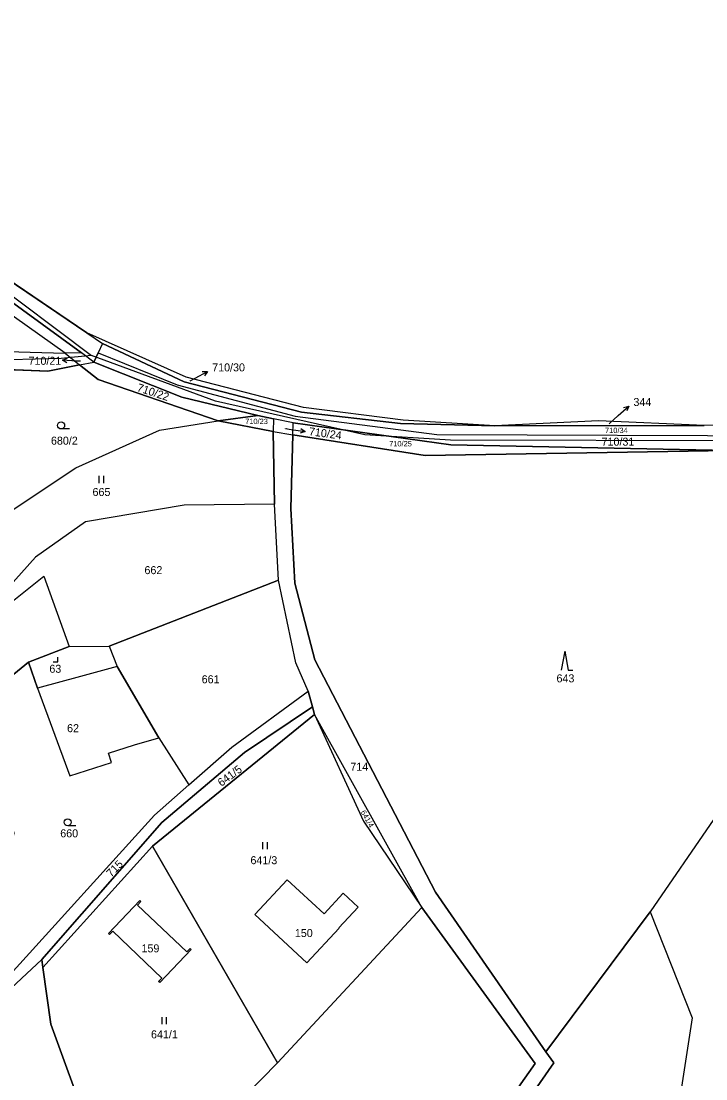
# Model space of a CAD drawing. Extents: x -590606 to -587796, y -1065936 to -1062515.
# Drawn here: x -589558.4 to -589413.2, y -1064760.8 to -1064536.2 of the extents above; entities that cross this region are included whole.
import ezdxf

# ---------------------------------------------------------------- set-up
doc = ezdxf.new("R2010")
doc.units = 0
for name, color, linetype in [('Cesty', 7, 'Continuous'), ('Parcela nároku', 7, 'Continuous'), ('Parcelní číslo', 7, 'Continuous'), ('Vnější obvod_ Studené', 7, 'Continuous'), ('Vrstva 30', 7, 'Continuous')]:
    doc.layers.add(name, color=color, linetype=linetype)

msp = doc.modelspace()

# ---------------------------------------------------------------- linework, layer by layer
at = {"layer": 'Cesty'}
for points in [[(-589892.17, -1064369.93), (-589875.26, -1064390.63), (-589869.59, -1064400.17), (-589860.61, -1064415.28), (-589855.62, -1064428.91), (-589851.76, -1064436.47), (-589835.09, -1064454.08), (-589818.14, -1064470.08), (-589809.98, -1064474.85), (-589789.91, -1064479.31), (-589769.84, -1064483.14), (-589746.37, -1064490.42), (-589728.15, -1064501.15), (-589708.7, -1064515.97), (-589695.75, -1064525.84), (-589673.94, -1064537.99), (-589648.4, -1064547.43), (-589623.17, -1064553.21), (-589602.26, -1064563.18), (-589592.55, -1064571.88), (-589566.17, -1064590.19), (-589543.56, -1064607.17)], [(-589312.39, -1064575.92), (-589318.72, -1064584.83), (-589335.76, -1064596.6), (-589354.95, -1064613.9), (-589370.21, -1064620.11), (-589392.14, -1064624.65), (-589405.6, -1064625.31), (-589467.35, -1064625.2), (-589485.5, -1064624.04), (-589517.23, -1064616.87), (-589543.56, -1064607.17), (-589549.94, -1064607.84), (-589566.34, -1064608.24), (-589595.98, -1064606.38), (-589632.73, -1064602.69), (-589650.77, -1064600.08), (-589699.72, -1064596.26), (-589711.59, -1064596.2), (-589764.62, -1064605.69), (-589799.36, -1064611.91)]]:
    msp.add_lwpolyline(points, dxfattribs=at)
at = {"layer": 'Parcela nároku'}
for points in [[(-589386.23, -1064621.24), (-589413.51, -1064622.05), (-589435.93, -1064621.07), (-589457.96, -1064622.14), (-589477.4, -1064620.92), (-589498.57, -1064618.24), (-589523.41, -1064611.81), (-589544.52, -1064602.39), (-589570.02, -1064585.07), (-589593.92, -1064567.75), (-589602.81, -1064558), (-589627.14, -1064547.63), (-589640.22, -1064546.2), (-589655.82, -1064541.47), (-589688.24, -1064525.96)], [(-589681.45, -1064532.18), (-589655.82, -1064541.47), (-589647.67, -1064545.57), (-589640.22, -1064546.2), (-589617.67, -1064553.05), (-589599.87, -1064563.44), (-589593.92, -1064567.75), (-589591.52, -1064570.55), (-589570.02, -1064585.07), (-589544.52, -1064602.39), (-589541.19, -1064604.66), (-589542.09, -1064606.65), (-589543.01, -1064608.6), (-589545.68, -1064606.61), (-589574.93, -1064585.33), (-589584.07, -1064579.7), (-589592.41, -1064573.65), (-589595.48, -1064570.57), (-589606.26, -1064560.21), (-589627.8, -1064551.78), (-589646.88, -1064549.01), (-589693.05, -1064528.65)], [(-589850.56, -1064625.55), (-589808.34, -1064612.83), (-589752.19, -1064600.19), (-589738.08, -1064597.9), (-589710.88, -1064593.56), (-589696.02, -1064593.97), (-589645.99, -1064597.91), (-589599.74, -1064604.8), (-589596.03, -1064605.35), (-589549.09, -1064606.72), (-589546.05, -1064609.19), (-589552.79, -1064610.5), (-589564.95, -1064610.02), (-589586.36, -1064609.18), (-589594.13, -1064607.9), (-589600.62, -1064606.83), (-589651.05, -1064601), (-589706.94, -1064597.01), (-589710.09, -1064597.48), (-589753, -1064605.14), (-589810.83, -1064617.52), (-589850.49, -1064629.2)], [(-589475.36, -1064794.48), (-589449.38, -1064757.57), (-589473.46, -1064724.46), (-589496.18, -1064683.43), (-589496.63, -1064681.82), (-589497.56, -1064678.5), (-589500.15, -1064672.47), (-589503.84, -1064654.9), (-589504.71, -1064638.79), (-589504.98, -1064623.35), (-589500.84, -1064624.06), (-589501.22, -1064639.68), (-589500.39, -1064655.52), (-589496.13, -1064671.82), (-589470.54, -1064721.2), (-589447.12, -1064755.09), (-589445.45, -1064757.41), (-589471.15, -1064794.54)]]:
    msp.add_lwpolyline(points, dxfattribs=at)
for points in [[(-589592.41, -1064573.65), (-589584.07, -1064579.7), (-589574.93, -1064585.33), (-589545.68, -1064606.61), (-589549.09, -1064606.72), (-589592.68, -1064575.78)], [(-589592.68, -1064575.78), (-589596.03, -1064605.35), (-589549.09, -1064606.72)], [(-589498.57, -1064618.24), (-589523.41, -1064611.81), (-589544.52, -1064602.39), (-589541.19, -1064604.66), (-589523.88, -1064612.81), (-589499, -1064619.25), (-589477.97, -1064621.63), (-589457.96, -1064622.14), (-589477.4, -1064620.92)], [(-589358.1, -1064617.56), (-589361.6, -1064613.55), (-589372.34, -1064619.94), (-589379.5, -1064620.44), (-589386.23, -1064621.24), (-589413.51, -1064622.05), (-589457.96, -1064622.14), (-589477.97, -1064621.63), (-589499, -1064619.25), (-589523.88, -1064612.81), (-589541.19, -1064604.66), (-589542.09, -1064606.65), (-589525.32, -1064613.43), (-589500.34, -1064620.07), (-589470.25, -1064623.98), (-589393.65, -1064624.26), (-589372.9, -1064622.03)], [(-589545.68, -1064606.61), (-589549.09, -1064606.72), (-589546.05, -1064609.19), (-589543.01, -1064608.6)], [(-589393.65, -1064624.26), (-589372.9, -1064622.03), (-589358.1, -1064617.56), (-589363.47, -1064621.18), (-589394.04, -1064627.1), (-589408.35, -1064627.34), (-589467.25, -1064626.15), (-589500.72, -1064621.47), (-589504.92, -1064620.61), (-589508.23, -1064619.91), (-589524.33, -1064616.05), (-589543.01, -1064608.6), (-589542.09, -1064606.65), (-589525.32, -1064613.43), (-589500.34, -1064620.07), (-589470.25, -1064623.98)], [(-589542.13, -1064612.29), (-589546.05, -1064609.19), (-589552.79, -1064610.5), (-589564.95, -1064610.02), (-589563.64, -1064643.14), (-589561.44, -1064640.72), (-589546.87, -1064631.05), (-589529.07, -1064623.08), (-589516.66, -1064621.08)], [(-589543.01, -1064608.6), (-589524.33, -1064616.05), (-589508.23, -1064619.91), (-589516.66, -1064621.08), (-589542.13, -1064612.29), (-589546.05, -1064609.19)], [(-589575.32, -1064655.99), (-589573.32, -1064653.79), (-589563.64, -1064643.14), (-589561.44, -1064640.72), (-589546.87, -1064631.05), (-589529.07, -1064623.08), (-589516.66, -1064621.08), (-589504.98, -1064623.35), (-589504.71, -1064638.79), (-589523.85, -1064638.97), (-589544.78, -1064642.49), (-589555.43, -1064650), (-589562.54, -1064658.03), (-589567.91, -1064663.13)], [(-589508.23, -1064619.91), (-589504.92, -1064620.61), (-589504.98, -1064623.35), (-589516.66, -1064621.08)], [(-589504.92, -1064620.61), (-589504.98, -1064623.35), (-589500.84, -1064624.06), (-589500.72, -1064621.47)], [(-589413.51, -1064622.05), (-589435.93, -1064621.07), (-589457.96, -1064622.14)], [(-589500.84, -1064624.06), (-589472.75, -1064628.4), (-589408.35, -1064627.34), (-589394.04, -1064627.1), (-589353.94, -1064621.82), (-589361.07, -1064630.25), (-589386.79, -1064662.08), (-589403.44, -1064690.75), (-589411.5, -1064705.67), (-589425, -1064725.38), (-589447.12, -1064755.09), (-589470.54, -1064721.2), (-589496.13, -1064671.82), (-589500.39, -1064655.52), (-589501.22, -1064639.68)], [(-589500.72, -1064621.47), (-589467.25, -1064626.15), (-589408.35, -1064627.34), (-589472.75, -1064628.4), (-589500.84, -1064624.06)], [(-589503.84, -1064654.9), (-589504.71, -1064638.79), (-589523.85, -1064638.97), (-589544.78, -1064642.49), (-589555.43, -1064650), (-589562.54, -1064658.03), (-589561.08, -1064660), (-589553.65, -1064654.07), (-589548.24, -1064668.99), (-589539.78, -1064668.95)], [(-589579.59, -1064674.92), (-589567.91, -1064663.13), (-589562.54, -1064658.03), (-589561.08, -1064660), (-589553.65, -1064654.07), (-589548.24, -1064668.99), (-589556.93, -1064672.33), (-589569.41, -1064682.53)], [(-589497.56, -1064678.5), (-589500.15, -1064672.47), (-589503.84, -1064654.9), (-589539.78, -1064668.95), (-589538.06, -1064673.24), (-589529.23, -1064688.37), (-589522.89, -1064698.36), (-589513.75, -1064690.35)], [(-589539.78, -1064668.95), (-589538.06, -1064673.24), (-589545.89, -1064675.38), (-589554.98, -1064677.87), (-589556.93, -1064672.33), (-589548.24, -1064668.99)], [(-589539.89, -1064691.66), (-589534.4, -1064689.91), (-589529.23, -1064688.37), (-589522.89, -1064698.36), (-589530.19, -1064704.81), (-589560.8, -1064738.7), (-589565.29, -1064732.38), (-589564.75, -1064729.88), (-589559.97, -1064708.63), (-589567.53, -1064686.1), (-589568.49, -1064683.25), (-589569.41, -1064682.53), (-589556.93, -1064672.33), (-589554.98, -1064677.87), (-589548.15, -1064696.48), (-589539.26, -1064693.64)], [(-589539.26, -1064693.64), (-589539.89, -1064691.66), (-589534.4, -1064689.91), (-589529.23, -1064688.37), (-589538.06, -1064673.24), (-589545.89, -1064675.38), (-589554.98, -1064677.87), (-589548.15, -1064696.48)], [(-589522.89, -1064698.36), (-589513.75, -1064690.35), (-589497.56, -1064678.5), (-589496.63, -1064681.82), (-589511.03, -1064691.51), (-589528.63, -1064706.39), (-589554.07, -1064735.46), (-589571.42, -1064751.62), (-589583.26, -1064760.02), (-589588.45, -1064763.67), (-589590.38, -1064760.46), (-589573.06, -1064749.58), (-589560.8, -1064738.7), (-589530.19, -1064704.81)], [(-589511.03, -1064691.51), (-589496.63, -1064681.82), (-589496.18, -1064683.43), (-589530.55, -1064711.43), (-589553.84, -1064737.2), (-589554.07, -1064735.46), (-589528.63, -1064706.39)], [(-589530.55, -1064711.43), (-589496.18, -1064683.43), (-589485.8, -1064706.13), (-589473.46, -1064724.46), (-589504.08, -1064757.44)], [(-589473.46, -1064724.46), (-589496.18, -1064683.43), (-589485.8, -1064706.13)], [(-589378.38, -1064737.45), (-589411.5, -1064705.67), (-589425, -1064725.38), (-589416.09, -1064747.85), (-589424.1, -1064799.94), (-589411.31, -1064785.43), (-589390.57, -1064758.82)], [(-589530.55, -1064711.43), (-589504.08, -1064757.44), (-589510.92, -1064764.47), (-589536.47, -1064792.4), (-589552.16, -1064749.21), (-589553.84, -1064737.2)], [(-589486.96, -1064724.35), (-589491.05, -1064728.74), (-589490.98, -1064728.81), (-589497.82, -1064736.18), (-589508.87, -1064725.9), (-589502.01, -1064718.53), (-589494.19, -1064725.81), (-589490.11, -1064721.42)], [(-589490.11, -1064721.42), (-589486.96, -1064724.35), (-589491.05, -1064728.74), (-589490.98, -1064728.81), (-589497.82, -1064736.18), (-589508.87, -1064725.9), (-589502.01, -1064718.53), (-589494.19, -1064725.81)], [(-589539.69, -1064730.2), (-589539.91, -1064729.99), (-589533.27, -1064722.95), (-589533.06, -1064723.17), (-589533.75, -1064723.91), (-589523.29, -1064733.86), (-589522.62, -1064733.11), (-589522.4, -1064733.33), (-589529.05, -1064740.37), (-589529.29, -1064740.17), (-589528.57, -1064739.41), (-589539.02, -1064729.45)], [(-589529.29, -1064740.17), (-589528.57, -1064739.41), (-589539.02, -1064729.45), (-589539.69, -1064730.2), (-589539.91, -1064729.99), (-589533.27, -1064722.95), (-589533.06, -1064723.17), (-589533.75, -1064723.91), (-589523.29, -1064733.86), (-589522.62, -1064733.11), (-589522.4, -1064733.33), (-589529.05, -1064740.37)], [(-589473.46, -1064724.46), (-589449.38, -1064757.57), (-589475.36, -1064794.48), (-589481.42, -1064802.93), (-589510.92, -1064764.47), (-589504.08, -1064757.44)], [(-589447.12, -1064755.09), (-589425, -1064725.38), (-589416.09, -1064747.85), (-589424.1, -1064799.94), (-589450.87, -1064826.05), (-589471.15, -1064794.54), (-589445.45, -1064757.41)], [(-589583.26, -1064760.02), (-589571.42, -1064751.62), (-589554.07, -1064735.46), (-589553.84, -1064737.2), (-589552.16, -1064749.21), (-589536.47, -1064792.4), (-589565.9, -1064825.54), (-589588.45, -1064763.67)]]:
    msp.add_lwpolyline(points, close=True, dxfattribs=at)
at = {"layer": 'Parcelní číslo'}
for p, q in [((-589546.71, -1064608.37), (-589549.7, -1064608.19)), ((-589545.88, -1064608.42), (-589546.71, -1064608.37)), ((-589522.57, -1064612.54), (-589521.56, -1064611.99)), ((-589521.56, -1064611.99), (-589518.92, -1064610.57)), ((-589431.76, -1064619.94), (-589429.54, -1064617.92)), ((-589433.71, -1064621.71), (-589431.76, -1064619.94)), ((-589502.34, -1064622.72), (-589501.14, -1064622.9)), ((-589501.14, -1064622.9), (-589498.17, -1064623.35))]:
    msp.add_line(p, q, dxfattribs=at)
for points in [[(-589548.74, -1064608.75), (-589549.7, -1064608.19), (-589548.68, -1064607.75)], [(-589520.04, -1064610.6), (-589518.92, -1064610.57), (-589519.56, -1064611.48)], [(-589430.62, -1064618.22), (-589429.54, -1064617.92), (-589429.94, -1064618.96)], [(-589499.09, -1064622.7), (-589498.17, -1064623.35), (-589499.24, -1064623.69)]]:
    msp.add_lwpolyline(points, dxfattribs=at)
at = {"layer": 'Vnější obvod_ Studené'}
for p, q in [((-589544.52, -1064602.39), (-589570.02, -1064585.07)), ((-589523.41, -1064611.81), (-589544.52, -1064602.39)), ((-589564.95, -1064610.02), (-589552.79, -1064610.5)), ((-589552.79, -1064610.5), (-589546.05, -1064609.19)), ((-589546.05, -1064609.19), (-589542.13, -1064612.29)), ((-589542.13, -1064612.29), (-589516.66, -1064621.08)), ((-589498.57, -1064618.24), (-589523.41, -1064611.81)), ((-589477.4, -1064620.92), (-589498.57, -1064618.24)), ((-589516.66, -1064621.08), (-589504.98, -1064623.35)), ((-589457.96, -1064622.14), (-589477.4, -1064620.92)), ((-589435.93, -1064621.07), (-589457.96, -1064622.14)), ((-589413.51, -1064622.05), (-589435.93, -1064621.07)), ((-589386.23, -1064621.24), (-589413.51, -1064622.05)), ((-589504.98, -1064623.35), (-589500.84, -1064624.06)), ((-589500.84, -1064624.06), (-589472.75, -1064628.4)), ((-589472.75, -1064628.4), (-589408.35, -1064627.34))]:
    msp.add_line(p, q, dxfattribs=at)
at = {"layer": 'Vrstva 30'}
for p, q in [((-589548.23, -1064622.8), (-589549.98, -1064622.8)), ((-589541.95, -1064632.78), (-589541.95, -1064634.28)), ((-589540.93, -1064634.28), (-589540.93, -1064632.78)), ((-589443.11, -1064670), (-589443.84, -1064674)), ((-589443.11, -1064670), (-589442.38, -1064674)), ((-589442.38, -1064674), (-589441.38, -1064674)), ((-589546.83, -1064707.08), (-589548.58, -1064707.08)), ((-589507.21, -1064710.57), (-589507.21, -1064712.07)), ((-589506.19, -1064712.07), (-589506.19, -1064710.57)), ((-589528.6, -1064747.71), (-589528.6, -1064749.21)), ((-589527.58, -1064749.21), (-589527.58, -1064747.71))]:
    msp.add_line(p, q, dxfattribs=at)
msp.add_lwpolyline([(-589551.65, -1064672.26), (-589550.65, -1064672.26), (-589550.65, -1064671.26)], dxfattribs=at)
for centre in [(-589549.98, -1064622.05), (-589548.58, -1064706.33)]:
    msp.add_circle(centre, 0.75, dxfattribs=at)

# ---------------------------------------------------------------- texts
at = {"layer": 'Parcela nároku'}
for s, height, p in [('710/21', 0.1, (-589546.06, -1064608.42)), ('710/30', 0.1, (-589522.77, -1064612.54)), ('710/23', 1.14, (-589510.92, -1064621.75)), ('710/24', 0.1, (-589502.54, -1064622.72)), ('710/34', 1.14, (-589434.56, -1064623.66)), ('344', 0.1, (-589433.82, -1064621.71)), ('680/2', 1.7, (-589552.13, -1064626.13)), ('710/25', 1.14, (-589480.37, -1064626.5)), ('710/31', 1.7, (-589435.3, -1064626.35)), ('665', 1.7, (-589543.31, -1064637.03)), ('662', 1.7, (-589532.29, -1064653.63)), ('63', 1.7, (-589552.47, -1064674.58)), ('661', 1.7, (-589520.15, -1064676.81)), ('643', 1.7, (-589444.86, -1064676.61)), ('62', 1.7, (-589548.71, -1064687.2)), ('714', 1.7, (-589488.61, -1064695.39)), ('660', 1.7, (-589550.16, -1064709.53)), ('641/3', 1.7, (-589509.8, -1064715.24)), ('150', 1.7, (-589500.38, -1064730.71)), ('159', 1.7, (-589532.92, -1064733.96)), ('641/1', 1.7, (-589530.9, -1064752.23))]:
    msp.add_text(s, height=height, dxfattribs=at).set_placement(p)
for s, height, rotation, p in [('710/22', 1.7, 341.7675, (-589534.01, -1064614.71)), ('641/5', 1.7, 36.6827, (-589515.97, -1064698.83)), ('641/4', 1.14, 299.4645, (-589486.45, -1064704.16)), ('715', 1.7, 45.5738, (-589539.34, -1064718.1))]:
    msp.add_text(s, height=height, rotation=rotation, dxfattribs=at).set_placement(p)
at = {"layer": 'Parcelní číslo'}
for s, p in [('710/21', (-589556.89, -1064609.17)), ('710/30', (-589517.92, -1064610.57)), ('344', (-589428.54, -1064617.92))]:
    msp.add_text(s, height=1.7, dxfattribs=at).set_placement(p)
msp.add_text('710/24', height=1.7, rotation=352.4433, dxfattribs=at).set_placement((-589497.47, -1064624.12))

doc.saveas('drawing.dxf')
